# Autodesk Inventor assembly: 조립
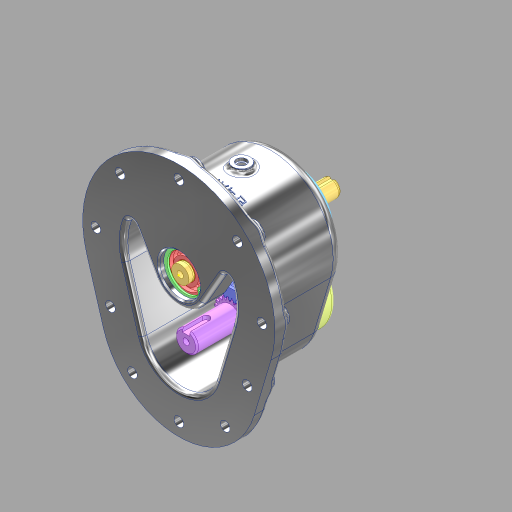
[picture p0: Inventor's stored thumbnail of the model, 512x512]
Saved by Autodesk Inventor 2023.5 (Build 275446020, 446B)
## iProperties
Created: 2026-03
Part Number: 조립
Document SubType Name: Assembly
Designer: mirae
Author: mirae
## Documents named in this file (14)
- C:\Users\mirae\Downloads\760303V1001\조립.iam
- C:\Users\mirae\Downloads\760303V1001\본체.ipt
- C:\Users\mirae\Downloads\760303V1001\6각 구멍붙이 볼트 M4x10\6각 구멍붙이 볼트 M4x10.ipt
- C:\Users\mirae\Downloads\760303V1001\C형 멈춤링 구멍용 28\C형 멈춤링 구멍용 28.ipt
- C:\Users\mirae\Downloads\760303V1001\C형 멈춤링 축용 12\C형 멈춤링 축용 12.ipt
- C:\Users\mirae\Downloads\760303V1001\기어 축\기어 축.ipt
- C:\Users\mirae\Downloads\760303V1001\깊은 홈 볼 베어링 6001\깊은 홈 볼 베어링 6001.ipt
- C:\Users\mirae\Downloads\760303V1001\상부 커버\상부 커버.ipt
- C:\Users\mirae\Downloads\760303V1001\스퍼 기어\스퍼 기어.ipt
- C:\Users\mirae\Downloads\760303V1001\오일 실 12 25 7\오일 실 12 25 7.ipt
- C:\Users\mirae\Downloads\760303V1001\축\축.ipt
- C:\Users\mirae\Downloads\760303V1001\칼라\칼라.ipt
- C:\Users\mirae\Downloads\760303V1001\평행 키 4x4x12\평행 키 4x4x12.ipt
- C:\Users\mirae\Downloads\760303V1001\하부 커버\하부 커버.ipt
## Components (9 placed, 4 different names)
1. 6각 구멍붙이 볼트 M4x10:1 — 각도:1
2. C형 멈춤링 구멍용 28:1 — 각도:10
3. C형 멈춤링 축용 12:1 — 각도:11
4. 하부 커버:1 — 각도:6
5. 6각 구멍붙이 볼트 M4x10:2 — 각도:3
6. 6각 구멍붙이 볼트 M4x10:3 — 각도:2
7. 6각 구멍붙이 볼트 M4x10:4 — 각도:7
8. 6각 구멍붙이 볼트 M4x10:5 — 각도:8
9. 6각 구멍붙이 볼트 M4x10:6 — 각도:9
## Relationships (9: Angle 9)
- 각도:1 [Angle]: 6각 구멍붙이 볼트 M4x10:1
- 각도:2 [Angle]: 6각 구멍붙이 볼트 M4x10:3
- 각도:3 [Angle]: 6각 구멍붙이 볼트 M4x10:2
- 각도:6 [Angle]: 하부 커버:1
- 각도:7 [Angle]: 6각 구멍붙이 볼트 M4x10:4
- 각도:8 [Angle]: 6각 구멍붙이 볼트 M4x10:5
- 각도:9 [Angle]: 6각 구멍붙이 볼트 M4x10:6
- 각도:10 [Angle]: C형 멈춤링 구멍용 28:1
- 각도:11 [Angle]: C형 멈춤링 축용 12:1
